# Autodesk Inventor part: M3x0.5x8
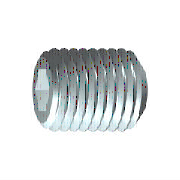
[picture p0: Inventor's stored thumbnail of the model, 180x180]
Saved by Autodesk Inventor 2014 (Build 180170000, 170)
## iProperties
IsCustomPart: 1
Company: 한국ATC센터
Created: 2009-02
Part Number: M3x0.5x8
Material: 강, 연강
Description: 6각 소켓 머리 없는 멈춤 나사
Document SubType Name: Modeling
Standard: KS B 1028
Designer: KYOUNG IL JANG
Standards Organization: KS
Language: ko-KR
Size Designation: 납작점M3x6
Categories: <MemberInstance><Categories><Category DisplayName="조임쇠" InternalName="e4da775c-781d-43d5-af7c-5136215cf5a6" Mnemonic="FSTN"><Category DisplayName="볼트" InternalN
Density: 7.86 g/cm^3
Mass: 0.293227 g
Surface Area: 0.779766 cm^2
Volume: 0.0373062 cm^3
Vendor: CBT Solutions
Appearance: 강철
Author: KYOUNG IL JANG
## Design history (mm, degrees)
sketch "스케치1"
  geometry: L1 (0, 0)-(3.5, 0); L2 (6, 0.866)-(6, 1.5); L3 (6, 1.5)-(0, 1.5); L4 (6, 0.866)-(4, 0.866); L5 (4, 0.866)-(3.5, 0); L6 (0, -0.3)-(0, 1.8) reference; L7 (0, 1.5)-(0, 0)
  constraints: 13 end point, 3 parallel, 1 collinear, 1 perpendicular, 1 point on line
  dimensions: "d0" = 2 distance of L2.start L4.end (= INTI); "d1" = 60 deg angle of L5 L1; "d2" = 3 diameter of L3 L1 (= NND); "d3" = 1.73205 diameter of L4 L1 (= 1.1547 x SW); "d5" = 6 distance from line of L2 L3.end (= NLG)
revolve "본체" sketch "스케치1" stored, may be unused: angle "d6" = 90 deg
sketch "스케치2"
  geometry: L1 (-0.433, 0.75)-(0.433, 0.75); L2 (0.433, 0.75)-(0.866, 0); L3 (0.866, 0)-(0.433, -0.75); L4 (0.433, -0.75)-(-0.433, -0.75); L5 (-0.433, -0.75)-(-0.866, 0); L6 (-0.866, 0)-(-0.433, 0.75); A1 r 0.866 centre (0, 0) between (-0.433, 0.75) and (0.433, 0.75) reference; 2 further points
  constraints: 12 end point, 2 point on circle, 1 coincident, 1 horizontal, 11 other
extrude "슬롯" join sketch "스케치2" taper "d9" = 0 deg; stored distance "d21" = 10
workaxis "Work Axis1"
workplane "Work Plane1"
body "Solid1"
chamfer "모따기1" distance "d7" = 0.30673 (= -0.5 x GD1 + 0.5 x NND); stored, may be unused: angle "d8" = 45 deg (= FAWI), second distance "d29" = 0.30673 (= -0.5 x GD1 + 0.5 x NND)
feature "스레드" dims "d11" = 6 (= NLG), "d12" = 0
chamfer "모따기2" distance "d13" = 0.30673 (= -0.5 x GD1 + 0.5 x NND); stored, may be unused: angle "d14" = 45 deg (= FAWI), second distance "d30" = 0.30673 (= -0.5 x GD1 + 0.5 x NND)
other parameters: "NND" = 3 [user parameter; used in 5 equation terms], "NLG" = 6 [user parameter; used in 2 equation terms], "INTI" = 2 [user parameter; used in 1 equation term], "FAWI" = 45 deg [user parameter; used in 2 equation terms], "SW" = 1.5 [user parameter; used in 2 equation terms], "GD1" = 2.38655 (= THREADDIA - 1.2269 x PTC) [user parameter; used in 4 equation terms], "d4" = 0, "FAWI1" = 45 deg [user parameter], "d15" = 0, "d31" = 0, "GUL" = 0.30673 (= 0.61345 x PTC) [user parameter], "SPD" = 2 [user parameter], "TOA" = 30 deg [user parameter], "THREADDIA" = 3 [user parameter; used in 1 equation term], "PTC" = 0.5 [user parameter; used in 4 equation terms], "GAL" = 0.30673 (= 0.61345 x PTC) [user parameter], "E0" = 1.7325 (= 1.155 x SW) [user parameter]
